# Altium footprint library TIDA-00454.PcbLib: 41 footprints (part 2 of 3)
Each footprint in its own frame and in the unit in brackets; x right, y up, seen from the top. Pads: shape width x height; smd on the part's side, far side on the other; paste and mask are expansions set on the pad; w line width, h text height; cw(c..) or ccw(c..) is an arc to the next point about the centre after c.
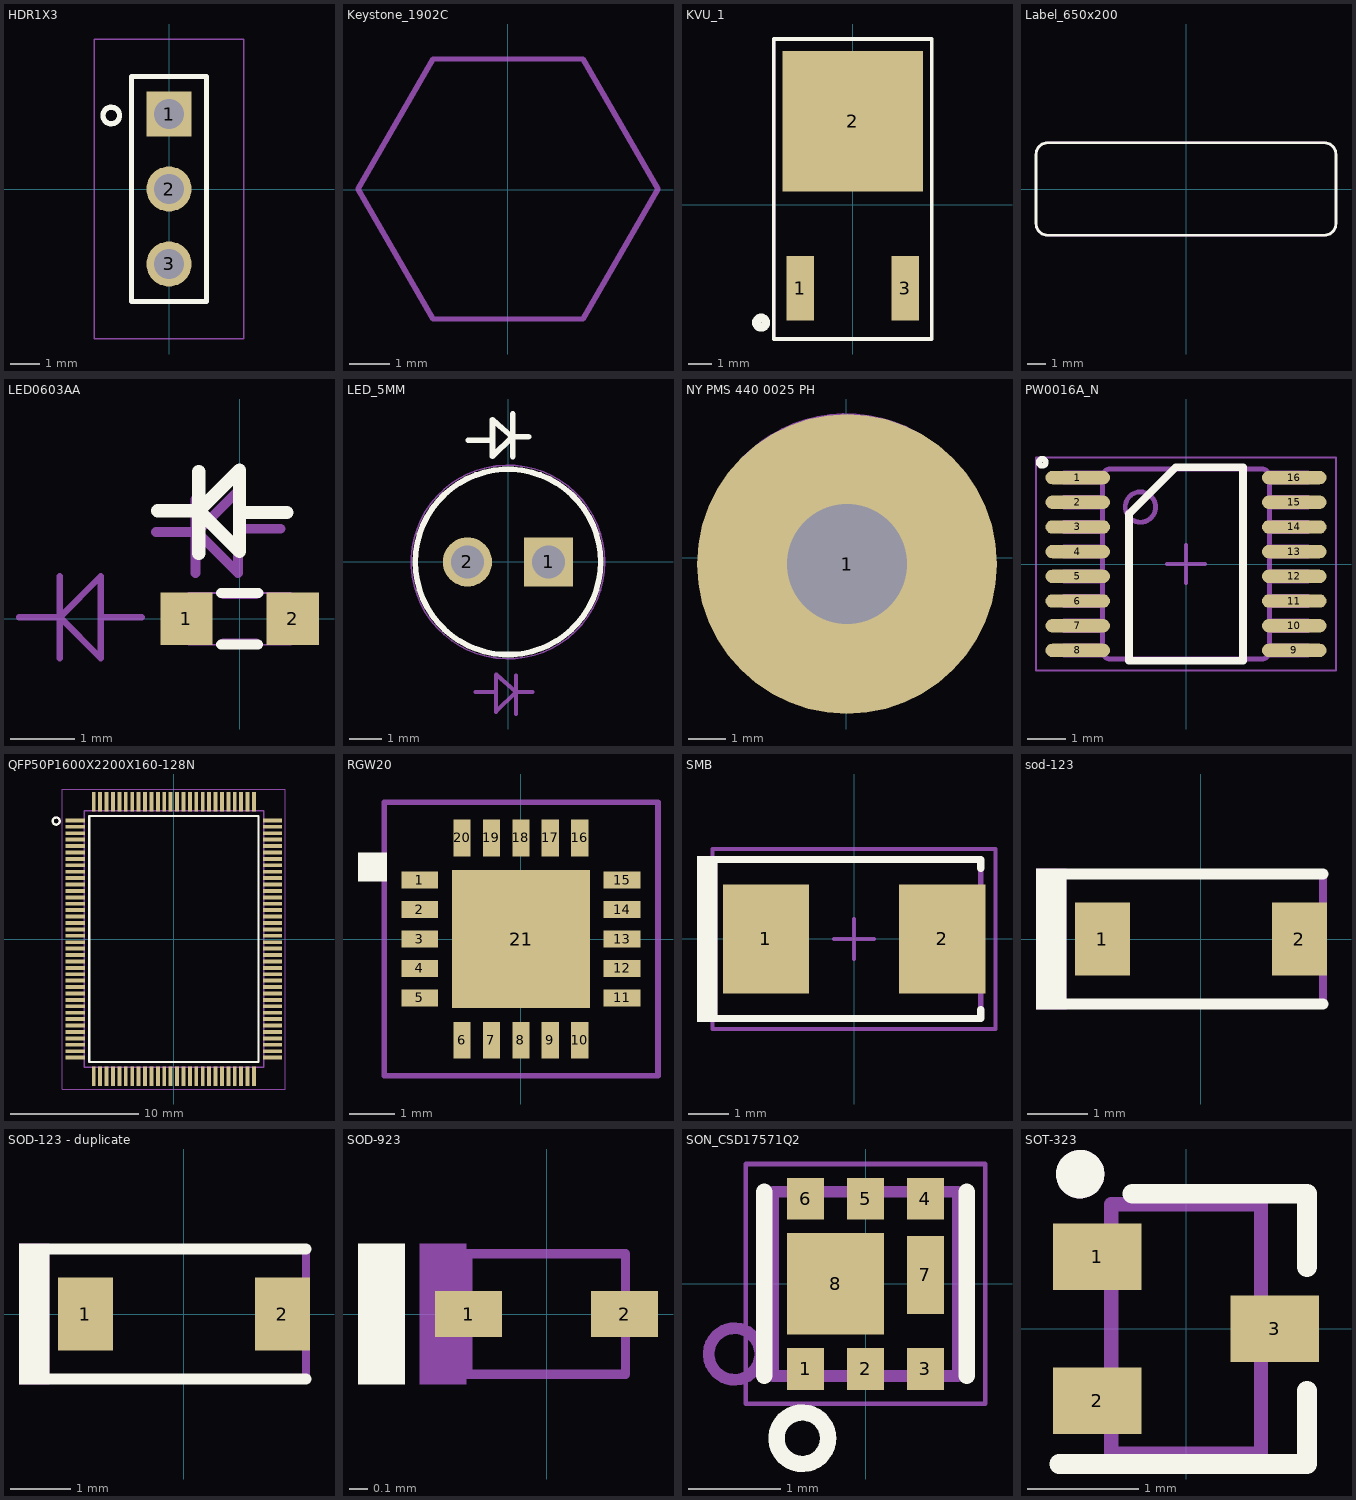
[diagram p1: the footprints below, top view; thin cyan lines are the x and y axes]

## HDR1X3 [mil] "HDR1X3"
pads (3):
  rect 60x60 / inner round 60 / far side rect 60x60 hole 40 mask+2.5: 1(0,100)
  round 60 hole 40 mask+2.5: 2(0,0) 3(0,-100)
Top Overlay:
  circle w7: c-77,98 r11
  lines w7: -50,-150 -50,150 50,150 50,-150 -50,-150
  text ".Designator" at -65,-50 h40
Bottom Overlay:
  lines w7: -50.48,-112.48 -50.48,-73.11 ; -50,-18.11 -50,21.26 ; -50,60.63 -50,100 ; -50,150 25,150 ; -47.89,-149.86 2.11,-149.86 ; 39.37,-150.58 50,-150.58 50,-118.69 ; 50,-66.06 50,-26.68 ; 50,21.26 50,60.63 ; 50,100 50,150
Mechanical 5:
  circle w5: c-77,98 r11
  lines w5: -50,-150 50,-150 50,150 -50,150 -50,-150
  text ".Designator" at -70,-10 h30
Mechanical 15:
  lines w1.97: -100,-200 100,-200 100,200 -100,200 -100,-200
3D body: height 1, standoff 0, extent -50,-150 50,150

## Keystone_1902C [mil] "Hex Standoff, 4-40 threaded, nylon"
height 500
pads (1):
  round 1 on Mech3 mask+2.5: 0(0,0)
Mechanical 5:
  lines w5: -145.29,0.49 -72.56,126.47 72.92,126.47 145.65,0.49 72.92,-125.49 -72.56,-125.49 -145.29,0.49
3D body: height 501, standoff 1, extent -144.95,-125.98 146,125.98

## KVU_1 [mm]
height 2.39
pads (3):
  rect 1.2x2.8 smd mask+0.064: 1(-2.29,-3.635) 3(2.29,-3.635)
  rect 6.096x6.096 smd mask+0.064: 2(0,3.635)
Top Overlay:
  circle w0.381: c-3.988,-5.131 r0.203
  lines w0.152: -3.429,-5.841 3.429,-5.841 3.429,7.216 -3.429,7.216 -3.429,-5.841
Mechanical 5:
  lines w0.127: -3.429,-5.841 -3.429,7.216 3.429,7.216 3.429,-5.841 -3.429,-5.841
  text ".Designator" at 0.381,-0.381 h0.76

## Label_650x200 [mil] "Thermal Transfer Label"
height 1
pads (1):
  round 1 on Mech13 mask+2.5: 0(0,0)
Top Overlay:
  lines w6: -325,-75 ccw(c-300,-75) -300,-100 300,-100 ccw(c300,-75) 325,-75 325,75 ccw(c300,75) 300,100 -300,100 ccw(c-300,75) -325,75 -325,-75
Mechanical 5:
  lines w5: -325,-75 ccw(c-300,-75) -300,-100 300,-100 ccw(c300,-75) 325,-75 325,75 ccw(c300,75) 300,100 -300,100 ccw(c-300,75) -325,75 -325,-75
  text ".Designator" at -43,-19.85 h32
3D body: height 1, standoff 0, extent -325.51,-100.51 325.51,100.51

## LED0603AA [mil]
height 35.43
pads (2):
  rect 32x32 smd mask+2.5: 1(-32.48,0) 2(32.48,0)
Top Overlay:
  lines w6: -11.42,-15.75 11.42,-15.75 ; -11.42,15.75 11.42,15.75
  lines w8: -50,66 -25,66 ; -25,40 -25,90 ; 4,65 29,65 ; -25,66 0,41 0,91 -25,66
Mechanical 5:
  lines w6: -51,53 -26,53 ; -27,28 -27,73 ; -10,-15 10,-15 ; -10,15 10,15 ; 0,55 25,55 ; -26,53 -1,78 -1,28 -26,53
  text ".Designator" at 87,9 h30
Mechanical 15:
  lines w1: -31.5,-15.75 -31.5,15.75 31.5,15.75 31.5,-15.75 -31.5,-15.75
  lines w3.94: -134.79,0.96 -109.79,0.96 ; -109.79,-24.04 -109.79,25.96 ; -84.79,0.96 -59.79,0.96 ; -109.79,0.96 -84.79,-24.04 -84.79,25.96 -109.79,0.96

## LED_5MM [mm] "LED, 5MM, RED, TH"
height 9
pads (2):
  rect 1.54x1.54 / inner round 1.54 / far side rect 1.54x1.54 hole 1.04 mask+0.064: 1(1.27,0)
  round 1.54 hole 1.04 mask+0.064: 2(-1.27,0)
Top Overlay:
  circle w0.178: c0,0 r2.9
  lines w0.178: -1.248,3.81 -0.61,3.81 ; 0.134,3.91 -0.483,4.445 -0.483,3.305 0.146,3.918 0.642,3.918 ; 0.152,3.302 0.152,4.629
  text ".Designator" at 1.549,2.794 h1.02
Bottom Overlay:
  lines w0.178: -2.899,0.001 ccw(c0.001,0.001) -2.51,-1.449 ; -2.51,1.451 cw(c0.001,0.001) -1.449,2.513 ; -1.449,-2.51 ccw(c0.001,0.001) 0.001,-2.899 ; 0.001,2.901 cw(c0.001,0.001) 1.451,2.513 ; 1.451,-2.51 ccw(c0.001,0.001) 2.513,-1.449 ; 2.513,1.451 cw(c0.001,0.001) 2.901,0.001
Mechanical 5:
  circle w0.127: c0,0 r2.9
  lines w0.127: -1.019,-4.064 -0.381,-4.064 ; -0.381,-4.696 -0.381,-3.529 ; -0.375,-4.677 0.254,-4.064 -0.363,-3.529 ; 0.254,-4.756 0.254,-3.556 ; 0.266,-4.064 0.762,-4.064
  text ".Designator" at -0.483,0.889 h0.76
Mechanical 15:
  circle w0.05: c0,0 r3.027
3D body: height 9, standoff 0, extent -2.9,-2.9 2.9,2.9

## NY PMS 440 0025 PH [mm] "4-40 nylon screw and mounting hole"
height 1.905
pads (1):
  round 8 hole 3.2 mask+0.064: 1(0.021,-0.172)
Mechanical 5:
  circle w0.127: c0,0 r3.789
3D body: height 2.69, standoff -8.74, extent -3.302,-3.3 3.296,3.3

## PW0016A_N [mm] "TSOP, 16-Leads, Body 5x4.4mm, Pitch 0.65mm, IPC Medium Density"
height 1.2
pads (16):
  oval 1.7x0.35 smd mask+0.064: 1(-2.85,2.275) 2(-2.85,1.625) 3(-2.85,0.975) 4(-2.85,0.325) 5(-2.85,-0.325) 6(-2.85,-0.975) 7(-2.85,-1.625) 8(-2.85,-2.275) 9(2.85,-2.275) 10(2.85,-1.625) 11(2.85,-0.975) 12(2.85,-0.325) 13(2.85,0.325) 14(2.85,0.975) 15(2.85,1.625) 16(2.85,2.275)
Top Overlay:
  circle w0.152: c-3.785,2.677 r0.092
  lines w0.2: -1.5,-2.55 1.5,-2.55 1.5,2.55 -0.275,2.55 -1.5,1.325 -1.5,-2.55
Mechanical 5:
  drawing of 202 lines, arcs and shapes, not listed
  text ".Designator" at 0.356,0.508 h0.76
Mechanical 15:
  lines w0.05: -3.95,-2.8 -3.95,2.8 3.95,2.8 3.95,-2.8 -3.95,-2.8
  lines w0.1: -0.5,0 0.5,0 ; 0,-0.5 0,0.5
3D body: height 0.98, standoff -0.02, extent -3.21,-2.5 3.21,2.5

## QFP50P1600X2200X160-128N [mm] "IC, 0.5MM PITCH, QFP-128P"
height 1.6
pads (128):
  rect 1.5x0.3 smd mask+0.058: 1(-7.7,9.25) 2(-7.7,8.75) 3(-7.7,8.25) 4(-7.7,7.75) 5(-7.7,7.25) 6(-7.7,6.75) 7(-7.7,6.25) 8(-7.7,5.75) 9(-7.7,5.25) 10(-7.7,4.75) 11(-7.7,4.25) 12(-7.7,3.75) 13(-7.7,3.25) 14(-7.7,2.75) 15(-7.7,2.25) 16(-7.7,1.75) 17(-7.7,1.25) 18(-7.7,0.75) 19(-7.7,0.25) 20(-7.7,-0.25) 21(-7.7,-0.75) 22(-7.7,-1.25) 23(-7.7,-1.75) 24(-7.7,-2.25) 25(-7.7,-2.75) 26(-7.7,-3.25) 27(-7.7,-3.75) 28(-7.7,-4.25) 29(-7.7,-4.75) 30(-7.7,-5.25) 31(-7.7,-5.75) 32(-7.7,-6.25) 33(-7.7,-6.75) 34(-7.7,-7.25) 35(-7.7,-7.75) 36(-7.7,-8.25) 37(-7.7,-8.75) 38(-7.7,-9.25) 65(7.7,-9.25) 66(7.7,-8.75) 67(7.7,-8.25) 68(7.7,-7.75) 69(7.7,-7.25) 70(7.7,-6.75) 71(7.7,-6.25) 72(7.7,-5.75) 73(7.7,-5.25) 74(7.7,-4.75) 75(7.7,-4.25) 76(7.7,-3.75) 77(7.7,-3.25) 78(7.7,-2.75) 79(7.7,-2.25) 80(7.7,-1.75) 81(7.7,-1.25) 82(7.7,-0.75) 83(7.7,-0.25) 84(7.7,0.25) 85(7.7,0.75) 86(7.7,1.25) 87(7.7,1.75) 88(7.7,2.25) 89(7.7,2.75) 90(7.7,3.25) 91(7.7,3.75) 92(7.7,4.25) 93(7.7,4.75) 94(7.7,5.25) 95(7.7,5.75) 96(7.7,6.25) 97(7.7,6.75) 98(7.7,7.25) 99(7.7,7.75) 100(7.7,8.25) 101(7.7,8.75) 102(7.7,9.25)
  rect 0.3x1.5 smd mask+0.058: 39(-6.25,-10.7) 40(-5.75,-10.7) 41(-5.25,-10.7) 42(-4.75,-10.7) 43(-4.25,-10.7) 44(-3.75,-10.7) 45(-3.25,-10.7) 46(-2.75,-10.7) 47(-2.25,-10.7) 48(-1.75,-10.7) 49(-1.25,-10.7) 50(-0.75,-10.7) 51(-0.25,-10.7) 52(0.25,-10.7) 53(0.75,-10.7) 54(1.25,-10.7) 55(1.75,-10.7) 56(2.25,-10.7) 57(2.75,-10.7) 58(3.25,-10.7) 59(3.75,-10.7) 60(4.25,-10.7) 61(4.75,-10.7) 62(5.25,-10.7) 63(5.75,-10.7) 64(6.25,-10.7) 103(6.25,10.7) 104(5.75,10.7) 105(5.25,10.7) 106(4.75,10.7) 107(4.25,10.7) 108(3.75,10.7) 109(3.25,10.7) 110(2.75,10.7) 111(2.25,10.7) 112(1.75,10.7) 113(1.25,10.7) 114(0.75,10.7) 115(0.25,10.7) 116(-0.25,10.7) 117(-0.75,10.7) 118(-1.25,10.7) 119(-1.75,10.7) 120(-2.25,10.7) 121(-2.75,10.7) 122(-3.25,10.7) 123(-3.75,10.7) 124(-4.25,10.7) 125(-4.75,10.7) 126(-5.25,10.7) 127(-5.75,10.7) 128(-6.25,10.7)
Top Overlay:
  circle w0.178: c-9.179,9.2 r0.279
  lines w0.178: -6.6,-9.6 6.6,-9.6 6.6,9.6 -6.6,9.6 -6.6,-9.6
  text ".Designator" at 1.473,-12.37 h1.02
Mechanical 5:
  circle w0.127: c-9.179,9.2 r0.279
  lines w0.127: -7,-10 7,-10 7,10 -7,10 -7,-10
  text ".Designator" at 0.254,0.254 h0.76
Mechanical 15:
  lines w0.05: -8.7,-11.7 -8.7,11.7 8.7,11.7 8.7,-11.7 -8.7,-11.7
3D body: height 1.6, standoff 0, extent -6.999,-9.999 6.999,9.999

## RGW20 [mil]
height 37.4
pads (21):
  rect 32x15 smd mask+2.5: 1(-88,51.2) 2(-88,25.6) 3(-88,0) 4(-88,-25.6) 5(-88,-51.2) 11(88,-51.2) 12(88,-25.6) 13(88,0) 14(88,25.6) 15(88,51.2)
  rect 15x32 smd mask+2.5: 6(-51.2,-88.1) 7(-25.6,-88.1) 8(0,-88.1) 9(25.6,-88.1) 10(51.2,-88.1) 16(51.2,87.9) 17(25.6,87.9) 18(0,87.9) 19(-25.6,87.9) 20(-51.2,87.9)
  rect 120x120 smd mask+2.5: 21(0.15,-0.05)
Top Overlay:
  region: -141.65,50.05 -116.65,50.05 -116.65,75.05 -141.65,75.05
Mechanical 5:
  lines w5: -118.8,-119 -118.8,119 119.2,119 119.2,-119 -118.8,-119
  text ".Designator" at -73,-20 h30
  text "*" at -102.3,72.9 h30

## SMB [mm] "Molded Diode, 2-Leads, Body 5.4x3.6mm, IPC Medium Density, based on OnSemi component dimensions"
height 2.45
pads (2):
  rect 2.159x2.743 smd mask+0.064: 1(-2.21,0) 2(2.21,0)
Top Overlay:
  rectangle: -3.937,-2.083 -3.429,2.083
  lines w0.178: -3.607,-1.994 3.175,-1.994 3.175,-1.765 ; -3.607,1.994 3.175,1.994 3.175,1.765
Mechanical 5:
  rectangle: -3.937,-2.083 -3.429,2.083
  lines w0.127: -3.607,-1.994 3.175,-1.994 3.175,-1.765 3.175,1.765 3.175,1.994 -3.607,1.994
  text ".Designator" at 0.889,0.254 h0.76
Mechanical 15:
  lines w0.1: -0.5,0 0.5,0 ; 0,-0.5 0,0.5 ; -3.55,-2.25 -3.55,2.25 3.55,2.25 3.55,-2.25 -3.55,-2.25
3D body: height 2.32, standoff 0.02, extent -2.7,-1.8 2.7,1.8

## sod-123 [mm] "On Semi recommended land pattern"
height 1.35
pads (2):
  rect 0.915x1.22 smd mask+0.064: 1(-1.637,0) 2(1.637,0)
Top Overlay:
  rectangle: -2.741,-1.168 -2.233,1.168
  lines w0.178: -2.413,-1.079 2.032,-1.079 ; -2.413,1.079 2.032,1.079
Mechanical 5:
  rectangle: -2.741,-1.168 -2.233,1.168
  lines w0.127: -2.413,-1.079 2.032,-1.079 2.032,1.079 -2.413,1.079
  text ".Designator" at 0.711,0.432 h0.76
3D body: height 1.35, standoff 0, extent -1.932,-0.9 1.932,0.9

## SOD-123 - duplicate [mm]
pads (2):
  rect 0.915x1.22 smd mask+0.064: 1(-1.637,0) 2(1.637,0)
Top Overlay:
  rectangle: -2.741,-1.168 -2.233,1.168
  lines w0.178: -2.413,-1.079 2.032,-1.079 ; -2.413,1.079 2.032,1.079
Mechanical 5:
  rectangle: -2.741,-1.168 -2.233,1.168
  lines w0.127: -2.413,-1.079 2.032,-1.079 2.032,1.079 -2.413,1.079
  text ".Designator" at 0.66,0.457 h0.76
3D body: height 1.35, standoff 0, extent -1.932,-0.9 1.932,0.9

## SOD-923 [mm] "ON-SEMI"
height 0.43
pads (2):
  rect 0.36x0.25 smd mask+0.064: 1(-0.42,0) 2(0.42,0)
Top Overlay:
  rectangle: -1.016,-0.381 -0.762,0.381
Mechanical 5:
  rectangle: -0.686,-0.381 -0.432,0.381
  lines w0.051: -0.425,-0.325 -0.425,0.325 0.425,0.325 0.425,-0.325 -0.425,-0.325
  text ".Designator" at 1.143,1.651 h0.76
3D body: height 0.44, standoff 0.4, extent -0.299,-0.324 -0.151,0.324
3D body: height 0.43, standoff 0, extent -0.445,-0.345 0.445,0.345

## SON_CSD17571Q2 [mm] "SON, MOSFET, N-CH, 30V, 22A, SON 2X2 MM"
height 0.85
pads (8):
  rect 0.4x0.455 smd mask+0.032: 1(-0.65,-0.923) 2(0,-0.923) 5(0,0.923) 6(-0.65,0.923)
  rect 0.4x0.455 smd mask+0.064: 3(0.65,-0.923) 4(0.65,0.923)
  rect 0.4x0.85 smd mask+0.038: 7(0.65,0.096)
  rect 1.05x1.1 smd mask+0.032: 8(-0.325,0)
Top Overlay:
  circle w0.178: c-0.686,-1.676 r0.279
  lines w0.178: -1.1,-1 -1.1,1 ; 1.1,-1 1.1,1
  text ".Designator" at 0.584,1.651 h1.02
Mechanical 5:
  circle w0.127: c-1.422,-0.762 r0.279
  lines w0.127: -1,-1 -1,1 1,1 1,-1 -1,-1
  text ".Designator" at 0.33,-0.635 h0.76
Mechanical 15:
  lines w0.05: -1.3,-1.3 1.3,-1.3 1.3,1.3 -1.3,1.3 -1.3,-1.3
3D body: height 0.85, standoff 0, extent -1,-1 1,0.975

## SOT-323 [mm] "Zetex recommended land pattern.  March 2007"
height 1.1
pads (3):
  rect 0.8x0.6 smd mask+0.064: 1(-0.8,0.65) 2(-0.8,-0.65) 3(0.8,0)
Top Overlay:
  circle w0.254: c-0.955,1.397 r0.092
  lines w0.178: -1.143,-1.219 1.092,-1.219 1.092,-0.559 ; -0.483,1.219 1.092,1.219 1.092,0.559
Mechanical 5:
  circle w0.254: c-0.955,1.397 r0.092
  lines w0.127: -1.125,-0.8 -1.125,-0.5 -0.975,-0.5 -0.935,-0.5 -0.884,-0.5 -0.725,-0.5 -0.675,-0.5 -0.675,-0.8 -0.725,-0.8 -0.884,-0.8 -0.935,-0.8 -0.975,-0.8 -1.125,-0.8 ; -1.125,0.5 -1.125,0.8 -0.975,0.8 -0.935,0.8 -0.884,0.8 -0.725,0.8 -0.675,0.8 -0.675,0.5 -0.725,0.5 -0.884,0.5 -0.935,0.5 -0.975,0.5 -1.125,0.5 ; -0.675,-1.125 -0.675,1.125 0.675,1.125 0.675,-1.125 -0.675,-1.125 ; 0.675,-0.15 0.725,-0.15 0.884,-0.15 0.935,-0.15 0.975,-0.15 1.125,-0.15 1.125,0.15 0.975,0.15 0.935,0.15 0.884,0.15 0.725,0.15 0.675,0.15 0.675,-0.15
  text ".Designator" at 0.356,-0.66 h0.76
3D body: height 1.13, standoff 0.02, extent -1.125,-1.125 1.125,1.125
